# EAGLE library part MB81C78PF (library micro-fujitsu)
MICROCONTROLLER/MEMORY DEVICE
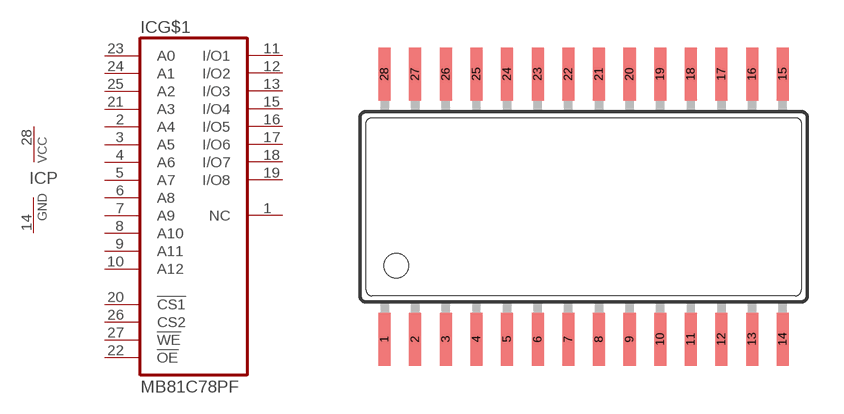
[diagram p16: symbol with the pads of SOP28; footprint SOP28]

Designator prefix IC; gates G$1=MB81C78 P=VCC-GND

## MB81C78PF (OC_FARNELL: unknown; OC_NEWARK: unknown)  [SOP28]
1  G$1:NC  nc
2  G$1:A4  in
3  G$1:A5  in
4  G$1:A6  in
5  G$1:A7  in
6  G$1:A8  in
7  G$1:A9  in
8  G$1:A10  in
9  G$1:A11  in
10  G$1:A12  in
11  G$1:I/O1
12  G$1:I/O2
13  G$1:I/O3
14  P:GND  pwr
15  G$1:I/O4  nc
16  G$1:I/O5
17  G$1:I/O6
18  G$1:I/O7
19  G$1:I/O8
20  G$1:!CS1  in
21  G$1:A3  in
22  G$1:!OE  in
23  G$1:A0  in
24  G$1:A1  in
25  G$1:A2  in
26  G$1:CS2  in
27  G$1:!WE  in
28  P:VCC  pwr

## Footprint SOP28 (pad centres in mm)
Small Outline Package
smd 0.5 x 2.2: 1 -8.255,-5.5; 2 -6.985,-5.5; 3 -5.715,-5.5; 4 -4.445,-5.5; 5 -3.175,-5.5; 6 -1.905,-5.5; 7 -0.635,-5.5; 8 0.635,-5.5; 9 1.905,-5.5; 10 3.175,-5.5; 11 4.445,-5.5; 12 5.715,-5.5; 13 6.985,-5.5; 14 8.255,-5.5; 15 8.255,5.5; 16 6.985,5.5; 17 5.715,5.5; 18 4.445,5.5; 19 3.175,5.5; 20 1.905,5.5; 21 0.635,5.5; 22 -0.635,5.5; 23 -1.905,5.5; 24 -3.175,5.5; 25 -4.445,5.5; 26 -5.715,5.5; 27 -6.985,5.5; 28 -8.255,5.5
